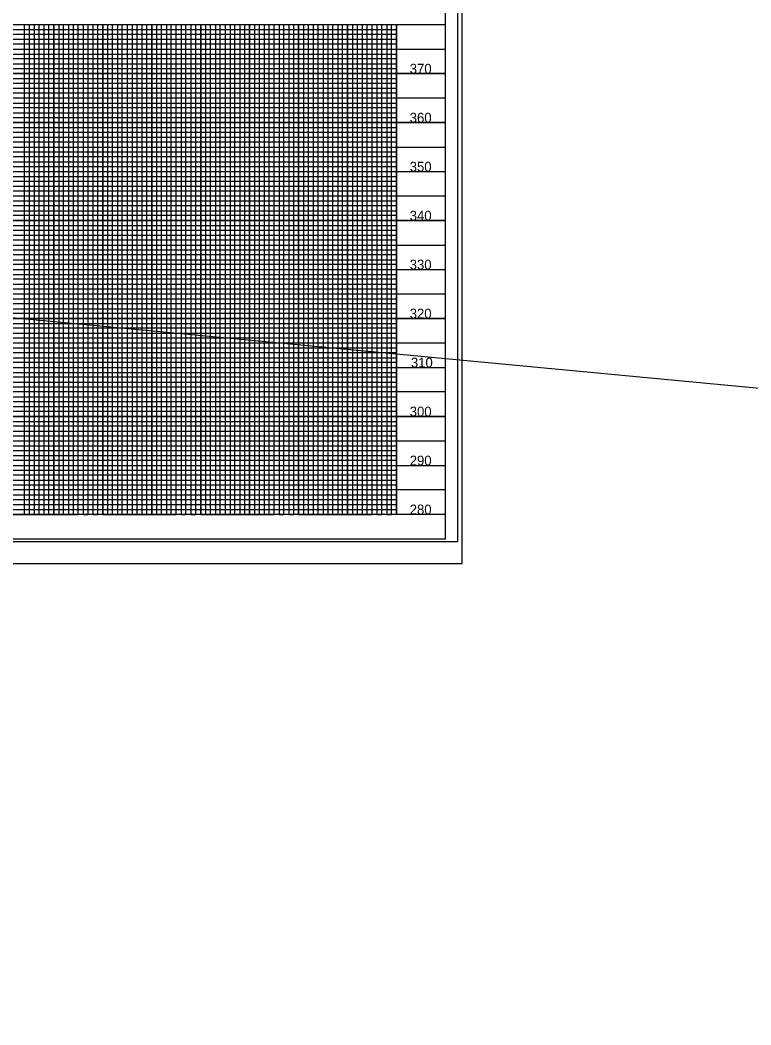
# Model space of a CAD drawing. Extents: x 571503 to 593215, y -77195 to -51828.
# Drawn here: x 584849 to 585595, y -54155 to -53129 of the extents above; entities that cross this region are included whole.
import ezdxf

# ---------------------------------------------------------------- set-up
doc = ezdxf.new("R2010")
doc.units = 0
for name, color, linetype in [('Exist Vertical Profile Vertical Axis Label', 7, 'Continuous'), ('Prop PFL Text', 7, 'Continuous'), ('Sheet Clip Boundary CELL', 7, 'Continuous'), ('Sheet DOT Grid CELL', 7, 'Continuous'), ('Sheet Plot Border Inside CELL', 7, 'Continuous'), ('Sheet Plot Border Outside CELL', 7, 'Continuous'), ('Sheet Profile CELL', 7, 'Continuous'), ('Sheet Profile Grid Major CELL', 7, 'Continuous'), ('Sheet Profile Grid Middle CELL', 7, 'Continuous'), ('Sheet Profile Grid Minor CELL', 7, 'Continuous')]:
    doc.layers.add(name, color=color, linetype=linetype)

msp = doc.modelspace()

# ---------------------------------------------------------------- linework, layer by layer
at = {"layer": 'Prop PFL Text'}
msp.add_line((571620.7, -52186.3), (592499.5, -54154.9), dxfattribs=at)
at = {"layer": 'Sheet Clip Boundary CELL'}
msp.add_lwpolyline([(583833.2, -53133.7), (585233.2, -53133.7), (585233.2, -53633.7), (583833.2, -53633.7)], close=True, dxfattribs=at)
at = {"layer": 'Sheet DOT Grid CELL'}
for p, q in [((583783.2, -53133.7), (585283.1, -53133.7)), ((584883.2, -53633.7), (584883.2, -53133.7)), ((584883.2, -53133.7), (584883.2, -53633.7)), ((584933.2, -53633.7), (584933.2, -53133.7)), ((584933.2, -53133.7), (584933.2, -53633.7)), ((584983.2, -53633.7), (584983.2, -53133.7)), ((584983.2, -53133.7), (584983.2, -53633.7)), ((585033.2, -53633.7), (585033.2, -53133.7)), ((585033.2, -53133.7), (585033.2, -53633.7)), ((585083.2, -53633.7), (585083.2, -53133.7)), ((585083.2, -53133.7), (585083.2, -53633.7)), ((585133.2, -53633.7), (585133.2, -53133.7)), ((585133.2, -53133.7), (585133.2, -53633.7)), ((585183.2, -53633.7), (585183.2, -53133.7)), ((585183.2, -53133.7), (585183.2, -53633.7)), ((585233.2, -53633.7), (585233.2, -53133.7)), ((585233.2, -53133.7), (585233.2, -53633.7)), ((583783.2, -53183.7), (585283.2, -53183.7)), ((583783.2, -53183.7), (585283.1, -53183.7)), ((583783.2, -53233.7), (585283.2, -53233.7)), ((583783.2, -53233.7), (585283.1, -53233.7)), ((583783.2, -53283.7), (585283.2, -53283.7)), ((583783.2, -53283.7), (585283.1, -53283.7)), ((583783.2, -53333.7), (585283.2, -53333.7)), ((583783.2, -53333.7), (585283.1, -53333.7)), ((583783.2, -53383.7), (585283.2, -53383.7)), ((583783.2, -53383.7), (585283.1, -53383.7)), ((583783.2, -53433.7), (585283.2, -53433.7)), ((583783.2, -53433.7), (585283.1, -53433.7)), ((583783.2, -53483.7), (585283.2, -53483.7)), ((583783.2, -53483.7), (585283.1, -53483.7)), ((583783.2, -53533.7), (585283.2, -53533.7)), ((583783.2, -53533.7), (585283.1, -53533.7)), ((583783.2, -53583.7), (585283.2, -53583.7)), ((583783.2, -53583.7), (585283.1, -53583.7))]:
    msp.add_line(p, q, dxfattribs=at)
at = {"layer": 'Sheet Plot Border Inside CELL'}
msp.add_lwpolyline([(583629.2, -53661.2), (585295.7, -53661.2), (585295.7, -52606.1), (583629.2, -52606.1)], close=True, dxfattribs=at)
at = {"layer": 'Sheet Plot Border Outside CELL'}
msp.add_lwpolyline([(583616.2, -53683.7), (585300.2, -53683.7), (585300.2, -52583.7), (583616.2, -52583.7)], close=True, dxfattribs=at)
at = {"layer": 'Sheet Profile CELL'}
for p, q in [((583783.2, -53133.7), (585283.2, -53133.7)), ((585283.2, -53633.7), (583783.2, -53633.7)), ((583783.2, -53658.7), (585283.2, -53658.7)), ((583616.2, -53683.7), (585300.2, -53683.7))]:
    msp.add_line(p, q, dxfattribs=at)
msp.add_lwpolyline([(585283.2, -52608.7), (583783.2, -52608.7), (583783.2, -53658.7), (585283.2, -53658.7)], close=True, dxfattribs=at)
at = {"layer": 'Sheet Profile Grid Major CELL'}
for p, q in [((584883.2, -53133.7), (584933.2, -53133.7)), ((584983.2, -53133.7), (585033.2, -53133.7)), ((585083.2, -53133.7), (585133.2, -53133.7)), ((585183.2, -53133.7), (585233.2, -53133.7)), ((585183.2, -53633.7), (585183.2, -53633.7))]:
    msp.add_line(p, q, dxfattribs=at)
for points in [[(584833.2, -53633.7), (584883.2, -53633.7), (584883.2, -53133.7), (584933.2, -53133.7), (584933.2, -53633.7), (584983.2, -53633.7), (584983.2, -53133.7), (585033.2, -53133.7), (585033.2, -53633.7), (585083.2, -53633.7), (585083.2, -53133.7), (585133.2, -53133.7), (585133.2, -53633.7), (585183.2, -53633.7), (585183.2, -53633.7), (585183.2, -53133.7), (585233.2, -53133.7), (585233.2, -53633.7)], [(585283.2, -53183.7), (583783.2, -53183.7)], [(585283.2, -53233.7), (583783.2, -53233.7), (583783.2, -53283.7), (585283.2, -53283.7)], [(585283.2, -53333.7), (583783.2, -53333.7), (583783.2, -53383.7), (585283.2, -53383.7)], [(585283.2, -53433.7), (583783.2, -53433.7), (583783.2, -53483.7), (585283.2, -53483.7)], [(585283.2, -53533.7), (583783.2, -53533.7), (583783.2, -53533.7), (583783.2, -53583.7), (585283.2, -53583.7)], [(585283.2, -53633.7), (583783.2, -53633.7)]]:
    msp.add_lwpolyline(points, dxfattribs=at)
at = {"layer": 'Sheet Profile Grid Middle CELL'}
for points in [[(584808.2, -53133.7), (584858.2, -53133.7), (584858.2, -53633.7), (584908.2, -53633.7), (584908.2, -53133.7), (584958.2, -53133.7), (584958.2, -53633.7), (585008.2, -53633.7), (585008.2, -53133.7), (585058.2, -53133.7), (585058.2, -53633.7), (585108.2, -53633.7), (585108.2, -53133.7), (585158.2, -53133.7), (585158.2, -53633.7), (585208.2, -53633.7), (585208.2, -53133.7)], [(583783.2, -53158.7), (585283.2, -53158.7)], [(585283.2, -53208.7), (583783.2, -53208.7), (583783.2, -53258.7), (585283.2, -53258.7)], [(585283.2, -53308.7), (583783.2, -53308.7), (583783.2, -53358.7), (585283.2, -53358.7)], [(585283.2, -53408.7), (583783.2, -53408.7), (583783.2, -53458.7), (585283.2, -53458.7)], [(585283.2, -53508.7), (583783.2, -53508.7), (583783.2, -53558.7), (585283.2, -53558.7)], [(585283.2, -53608.7), (583783.2, -53608.7)]]:
    msp.add_lwpolyline(points, dxfattribs=at)
at = {"layer": 'Sheet Profile Grid Minor CELL'}
for p, q in [((583833.2, -53138.7), (585233.2, -53138.7)), ((585233.2, -53143.7), (583833.2, -53143.7)), ((583833.2, -53148.7), (585233.2, -53148.7)), ((585233.2, -53153.7), (583833.2, -53153.7)), ((583833.2, -53163.7), (585233.2, -53163.7)), ((585233.2, -53168.7), (583833.2, -53168.7)), ((583833.2, -53173.7), (585233.2, -53173.7)), ((585233.2, -53178.7), (583833.2, -53178.7)), ((583833.2, -53188.7), (585233.2, -53188.7)), ((585233.2, -53193.7), (583833.2, -53193.7)), ((583833.2, -53198.7), (585233.2, -53198.7)), ((585233.2, -53203.7), (583833.2, -53203.7)), ((583833.2, -53213.7), (585233.2, -53213.7)), ((585233.2, -53218.7), (583833.2, -53218.7)), ((583833.2, -53223.7), (585233.2, -53223.7)), ((585233.2, -53228.7), (583833.2, -53228.7)), ((583833.2, -53238.7), (585233.2, -53238.7)), ((585233.2, -53243.7), (583833.2, -53243.7)), ((583833.2, -53248.7), (585233.2, -53248.7)), ((585233.2, -53253.7), (583833.2, -53253.7)), ((583833.2, -53263.7), (585233.2, -53263.7)), ((585233.2, -53268.7), (583833.2, -53268.7)), ((583833.2, -53273.7), (585233.2, -53273.7)), ((585233.2, -53278.7), (583833.2, -53278.7)), ((583833.2, -53288.7), (585233.2, -53288.7)), ((585233.2, -53293.7), (583833.2, -53293.7)), ((583833.2, -53298.7), (585233.2, -53298.7)), ((585233.2, -53303.7), (583833.2, -53303.7)), ((583833.2, -53313.7), (585233.2, -53313.7)), ((585233.2, -53318.7), (583833.2, -53318.7)), ((583833.2, -53323.7), (585233.2, -53323.7)), ((585233.2, -53328.7), (583833.2, -53328.5)), ((583833.2, -53338.7), (585233.2, -53338.7)), ((585233.2, -53343.7), (583833.2, -53343.7)), ((583833.2, -53348.7), (585233.2, -53348.7)), ((585233.2, -53353.7), (583833.2, -53353.7)), ((583833.2, -53363.7), (585233.2, -53363.7)), ((585233.2, -53368.7), (583833.2, -53368.7)), ((583833.2, -53373.7), (585233.2, -53373.7)), ((585233.2, -53378.7), (583833.2, -53378.7)), ((583833.2, -53388.7), (585233.2, -53388.7)), ((585233.2, -53393.7), (583833.2, -53393.7)), ((583833.2, -53398.7), (585233.2, -53398.7)), ((585233.2, -53403.7), (583833.2, -53403.7)), ((583833.2, -53413.7), (585233.2, -53413.7)), ((585233.2, -53418.7), (583833.2, -53418.7)), ((583833.2, -53423.7), (585233.2, -53423.7)), ((585233.2, -53428.7), (583833.2, -53428.7)), ((583833.2, -53438.7), (585233.2, -53438.7)), ((585233.2, -53443.7), (583833.2, -53443.7)), ((583833.2, -53448.7), (585233.2, -53448.7)), ((585233.2, -53453.7), (583833.2, -53453.7)), ((583833.2, -53463.7), (585233.2, -53463.7)), ((585233.2, -53468.7), (583833.2, -53468.7)), ((583833.2, -53473.7), (585233.2, -53473.7)), ((585233.2, -53478.7), (583833.2, -53478.7)), ((583833.2, -53488.7), (585233.2, -53488.7)), ((585233.2, -53493.7), (583833.2, -53493.7)), ((583833.2, -53498.7), (585233.2, -53498.7)), ((585233.2, -53503.7), (583833.2, -53503.7)), ((583833.2, -53513.7), (585233.2, -53513.7)), ((585233.2, -53518.7), (583833.2, -53518.7)), ((583833.2, -53523.7), (585233.2, -53523.7)), ((585233.2, -53528.7), (583833.2, -53528.7)), ((583833.2, -53538.7), (585233.2, -53538.7)), ((585233.2, -53543.7), (583833.2, -53543.7)), ((583833.2, -53548.7), (585233.2, -53548.7)), ((585233.2, -53553.7), (583833.2, -53553.7)), ((583833.2, -53563.7), (585233.2, -53563.7)), ((585233.2, -53568.7), (583833.2, -53568.7)), ((583833.2, -53573.7), (585233.2, -53573.7)), ((585233.2, -53578.7), (583833.2, -53578.7)), ((583833.2, -53588.7), (585233.2, -53588.7)), ((585233.2, -53593.7), (583833.2, -53593.7)), ((583833.2, -53598.7), (585233.2, -53598.7)), ((585233.2, -53603.7), (583833.2, -53603.7)), ((583833.2, -53613.7), (585233.2, -53613.7)), ((585233.2, -53618.7), (583833.2, -53618.7)), ((583833.2, -53623.7), (585233.2, -53623.7)), ((583833.2, -53628.7), (585233.2, -53628.7)), ((585233.2, -53628.7), (585233.2, -53628.7))]:
    msp.add_line(p, q, dxfattribs=at)
for points in [[(584848.2, -53633.7), (584853.2, -53633.7), (584853.2, -53133.7), (584863.2, -53133.7), (584863.2, -53633.7), (584868.2, -53633.7), (584868.2, -53133.7), (584873.2, -53133.7), (584873.2, -53633.7), (584878.2, -53633.7), (584878.2, -53133.7), (584888.2, -53133.7), (584888.2, -53633.7), (584893.2, -53633.7), (584893.2, -53133.7), (584898.2, -53133.7), (584898.2, -53633.7), (584903.2, -53633.7), (584903.2, -53133.7), (584913.2, -53133.7), (584913.2, -53633.7), (584918.2, -53633.7), (584918.2, -53133.7), (584923.2, -53133.7), (584923.2, -53633.7), (584928.2, -53633.7), (584928.2, -53133.7), (584938.2, -53133.7), (584938.2, -53633.7), (584943.2, -53633.7), (584943.2, -53133.7), (584948.2, -53133.7), (584948.2, -53633.7), (584953.2, -53633.7), (584953.2, -53133.7), (584963.2, -53133.7), (584963.2, -53633.7), (584968.2, -53633.7), (584968.2, -53133.7), (584973.2, -53133.7), (584973.2, -53633.7)], [(584973.2, -53633.7), (584978.2, -53633.7), (584978.2, -53133.7), (584988.2, -53133.7), (584988.2, -53633.7), (584993.2, -53633.7), (584993.2, -53133.7), (584998.2, -53133.7), (584998.2, -53633.7), (585003.2, -53633.7), (585003.2, -53133.7), (585013.2, -53133.7), (585013.2, -53633.7), (585018.2, -53633.7), (585018.2, -53133.7), (585023.2, -53133.7), (585023.2, -53633.7), (585028.2, -53633.7), (585028.2, -53133.7), (585038.2, -53133.7), (585038.2, -53633.7), (585043.2, -53633.7), (585043.2, -53133.7), (585048.2, -53133.7), (585048.2, -53633.7), (585053.2, -53633.7), (585053.2, -53133.7), (585063.2, -53133.7), (585063.2, -53633.7), (585068.2, -53633.7), (585068.2, -53133.7), (585073.2, -53133.7), (585073.2, -53633.7), (585078.2, -53633.7), (585078.2, -53133.7), (585088.2, -53133.7), (585088.2, -53633.7), (585093.2, -53633.7), (585093.2, -53133.7), (585098.2, -53133.7), (585098.2, -53633.7), (585103.2, -53633.7), (585103.2, -53133.7), (585113.2, -53133.7), (585113.2, -53633.7), (585118.2, -53633.7), (585118.2, -53133.7), (585123.2, -53133.7), (585123.2, -53633.7), (585128.2, -53633.7), (585128.2, -53133.7), (585138.2, -53133.7), (585138.2, -53633.7), (585143.2, -53633.7), (585143.2, -53133.7), (585148.2, -53133.7), (585148.2, -53633.7), (585153.2, -53633.7), (585153.2, -53133.7), (585163.2, -53133.7), (585163.2, -53633.7), (585168.2, -53633.7), (585168.2, -53133.7), (585173.2, -53133.7), (585173.2, -53633.7), (585178.2, -53633.7), (585178.2, -53133.7), (585188.2, -53133.7), (585188.2, -53633.7), (585193.2, -53633.7), (585193.2, -53133.7), (585198.2, -53133.7), (585198.2, -53633.7), (585203.2, -53633.7), (585203.2, -53133.7), (585213.2, -53133.7), (585213.2, -53633.7), (585218.2, -53633.7), (585218.2, -53133.7), (585223.2, -53133.7), (585223.2, -53633.7), (585228.2, -53633.7), (585228.2, -53133.7), (585233.2, -53133.7)]]:
    msp.add_lwpolyline(points, dxfattribs=at)

# ---------------------------------------------------------------- texts
at = {"layer": 'Exist Vertical Profile Vertical Axis Label'}
for s, p in [('370', (585246.7, -53183.7)), ('360', (585246.7, -53233.7)), ('350', (585246.7, -53283.7)), ('340', (585246.7, -53333.7)), ('330', (585246.7, -53383.7)), ('330', (585246.7, -53383.7)), ('320', (585246.7, -53433.7)), ('320', (585246.7, -53433.7)), ('310', (585247.9, -53483.7)), ('310', (585247.9, -53483.7)), ('300', (585246.7, -53533.7)), ('300', (585246.7, -53533.7)), ('290', (585246.7, -53583.7)), ('290', (585246.7, -53583.7)), ('280', (585246.7, -53633.7)), ('280', (585246.7, -53633.7))]:
    msp.add_text(s, height=10, dxfattribs=at).set_placement(p)

doc.saveas('drawing.dxf')
